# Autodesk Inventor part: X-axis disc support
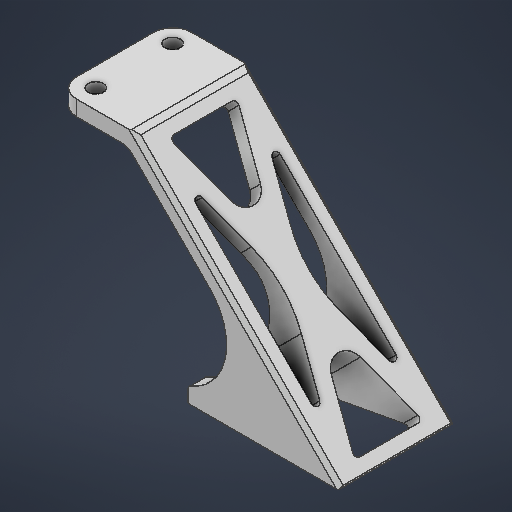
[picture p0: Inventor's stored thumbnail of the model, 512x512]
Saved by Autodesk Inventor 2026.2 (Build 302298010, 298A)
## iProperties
Created: 2026-04
Part Number: X-axis disc support
Material: 일반
Document SubType Name: Modeling
Designer: work
Density: 1 g/cm^3
Appearance: 기본값
Author: work
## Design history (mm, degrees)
sketch "스케치1"
  geometry: L1 (0, 10)-(0, -10); L2 (-5, 10)-(-5, -10); L3 (5, -10)-(5, 10); L4 (0, 15)-(-15, 15); L5 (-15, 15)-(-15, -15); L6 (-15, -15)-(0, -15); L7 (0, -15)-(0, 15); C1 r 2 at (0, 10); C2 r 2 at (0, -10); A1 r 5 centre (0, 10) between (5, 10) and (-5, 10); A2 r 5 centre (0, -10) between (-5, -10) and (5, -10); 2 further points
  constraints: 16 end point, 5 point on circle, 4 centre point, 4 tangent, 3 parallel, 2 coincident, 1 horizontal, 1 midpoint, 1 perpendicular, 1 vertical
  dimensions: "d0" = 10 distance of point (0, 0) L1.end; "d1" = 10 diameter of A2; "d2" = 4 diameter of C1; "d3" = 4 diameter of C2; "d4" = 15 distance of L6.end L5.end; "d5" = 30 distance of L4.end L5.end
extrude "돌출1" new body sketch "스케치1" distance "d6" = 4; taper "d7" = 0 deg
sketch "스케치2"
  geometry: L1 (15, 0)-(15, 4) reference; L2 (15, 4)-(69, -50); L3 (69, -50)-(29, -50); L4 (29, -50)-(29, -46); L5 (29, -46)-(59.343, -46); L6 (59.343, -46)-(13.343, 0); L7 (0, 0)-(15, 0) reference; L8 (15, 0)-(15, 4) reference; L9 (0, 4)-(15, 4) reference; L10 (0, 0)-(0, 4) reference; L11 (0, 0)-(15, 0) reference; 2 further points
  constraints: 10 end point, 3 perpendicular, 1 parallel, 1 point on line
  dimensions: "d8" = 4 distance between parallel lines of L6 L2; "d9" = 135 deg angle of L7 L6; "d10" = 50 distance between parallel lines of L7 L3; "d11" = 4 distance between parallel lines of L3 L5; "d12" = 40 distance from line of L2.end L4
extrude "돌출2" join sketch "스케치2" stored distance "d13" = 4; taper "d14" = 0 deg
fillet "모깎기1" dims "d15" = 15
fillet "모깎기2" dims "d16" = 4
chamfer "모따기1" distance "d17" = 1; stored, may be unused: second distance "d18" = 2, angle "d19" = 45 deg
sketch "스케치3"
  geometry: L1 (0, 0)-(-74.368, 0) reference; L2 (0, 28)-(0, 0) reference; L3 (-74.368, 28)-(0, 28) reference; L4 (-74.368, 0)-(-74.368, 28) reference; L5 (-3, 3)-(-71.368, 3); L6 (-71.368, 3)-(-71.368, 25); L7 (-71.368, 25)-(-3, 25); L8 (-3, 25)-(-3, 3); L9 (-3, 25)-(-71.368, 3); L10 (-71.368, 25)-(-3, 3); L11 (-64.838, 3)-(-3, 22.899); L12 (-3, 5.101)-(-64.838, 25); L13 (-9.529, 25)-(-71.368, 5.101); L14 (-9.529, 3)-(-71.368, 22.899); A1 r 4 centre (-17.596, 14) between (-18.822, 17.808) and (-18.822, 10.192); A2 r 4 centre (-56.771, 14) between (-55.546, 10.192) and (-55.546, 17.808); A3 r 30 centre (-37.184, -19.616) between (-27.994, 8.942) and (-46.373, 8.942); A4 r 30 centre (-37.184, 47.616) between (-46.373, 19.058) and (-27.994, 19.058); 1 further point
  constraints: 20 end point, 16 point on line, 8 point on circle, 8 tangent, 4 centre point, 4 parallel, 3 other
  dimensions: "d20" = 3 distance between parallel lines of L2 L8; "d22" = 4 distance between parallel lines of L12 L14; "d23" = 2 distance between parallel lines of L14 L10; "d24" = 2 distance between parallel lines of L13 L9; "d25" = 2 distance between parallel lines of L9 L11; "d26" = 4 radius of A1; "d27" = 4 radius of A2; "d28" = 30 radius of A4; "d29" = 30 radius of A3
extrude "돌출3" cut sketch "스케치3" extent not by distance; stored distance "d30" = 0; taper "d31" = 0 deg
fillet "모깎기3" dims "d32" = 1
node "솔리드1"
node "투영된 루프1"
node "투영된 루프2"
